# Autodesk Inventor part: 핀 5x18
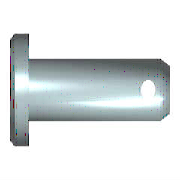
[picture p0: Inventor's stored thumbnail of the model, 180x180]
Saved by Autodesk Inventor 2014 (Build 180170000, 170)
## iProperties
Created: 2012-02
Part Number: 핀 5x18
Material: 강철
Description: 머리가 있는 클레비스 핀
Document SubType Name: Modeling
Standard: ISO 2341
Designer: test
Standard Revision: Second edition 1986-11-01
Standards Organization: ISO
Language: ko-KR
Size Designation: B - 5 x 18
Categories: <MemberInstance><Categories><Category DisplayName="조임쇠" InternalName="e4da775c-781d-43d5-af7c-5136215cf5a6" Mnemonic="FSTN"><Category DisplayName="핀" InternalNa
Density: 7.85 g/cm^3
Appearance: 주황색
IsCustomPart: 1
Author: test
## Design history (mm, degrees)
sketch "스케치1"
  geometry: L1 (-1.6, 0)-(-1.6, 4); L2 (-1.6, 4)-(0, 4); L3 (0, 4)-(0, 2.5); L4 (0, 2.5)-(18, 2.5); L5 (18, 2.5)-(18, 0); L6 (-1.6, 0)-(18, 0); L7 (-4, 0)-(17, 0) reference; L8 (0, -0.98)-(0, 3.08) reference; C1 r 0.6 at (15.1, 0)
  constraints: 12 end point, 3 parallel, 2 collinear, 2 perpendicular, 1 centre point, 1 point on line, 1 vertical
  dimensions: "d0" = 5 diameter of L4 L6 (= NND); "d1" = 8 diameter of L2 L6 (= KOD); "d2" = 1.6 distance of L1.end L2.end (= KOH); "d3" = 18 distance of L3.end L4.end (= NLG); "d5" = 2.9 distance from line of L5 C1.centre (= DIST); "d6" = 1.2 diameter of C1 (= BOR)
revolve "본체" stored, may be unused: angle "d4" = 90 deg
extrude "구멍" cut sketch "스케치1" stored distance "d7" = 5 (= NND); taper "d8" = 0 deg
workaxis "Work Axis1"
workplane "Work Plane1"
body "Solid1"
chamfer "모따기1" distance "d9" = 1 (= PHH2); stored, may be unused: angle "d10" = 45 deg (= FAWI2), second distance "d16" = 1 (= PHH2)
chamfer "모따기2" distance "d11" = 2 (= PHH1); stored, may be unused: angle "d12" = 30 deg (= FAWI1), second distance "d17" = 2 (= PHH1)
other parameters: "PHH1" = 2 [user parameter; used in 2 equation terms], "PHH2" = 1 [user parameter; used in 2 equation terms], "KOD" = 8 [user parameter; used in 1 equation term], "KOH" = 1.6 [user parameter; used in 1 equation term], "NND" = 5 [user parameter; used in 2 equation terms], "FAWI1" = 30 deg [user parameter; used in 1 equation term], "FAWI2" = 45 deg [user parameter; used in 1 equation term], "DIST" = 2.9 [user parameter; used in 1 equation term], "BOR" = 1.2 [user parameter; used in 1 equation term], "NLG" = 18 [user parameter; used in 1 equation term], "d13" = 0, "d14" = 0, "d27" = 0, "d28" = 0, "d29" = 0, "d30" = 0, "d31" = 0
